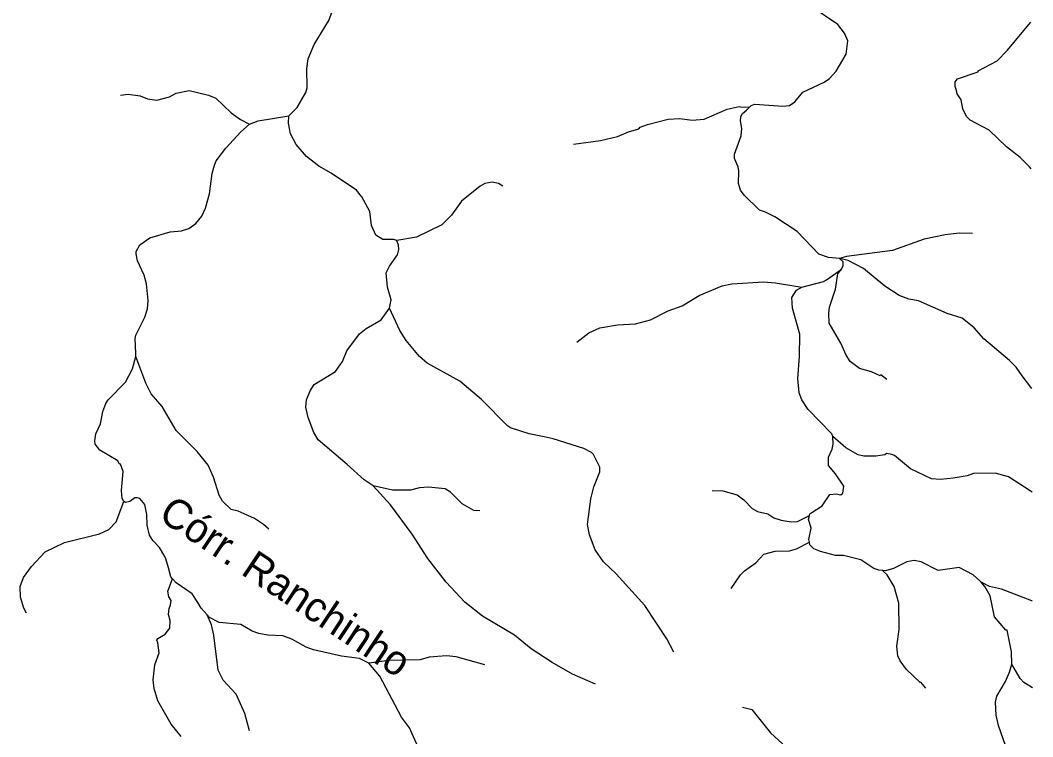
# Model space of a CAD drawing. Extents: x 393 to 446.6, y 8175.5 to 8231.
# Drawn here: x 441.14 to 446.6, y 8192.41 to 8196.27 of the extents above; entities that cross this region are included whole.
import ezdxf
from ezdxf.enums import TextEntityAlignment as Align

# ---------------------------------------------------------------- set-up
doc = ezdxf.new("R2010")
doc.units = 0
doc.header["$LTSCALE"] = 0.064
doc.linetypes.add('LONG_DASHED', pattern=[7.5, 6, -1.5])
doc.layers.add('61', color=7, linetype='Continuous')
doc.layers.add('7', color=7, linetype='Continuous', lineweight=25)
doc.layers.add('9', color=7, linetype='LONG_DASHED', lineweight=25)

msp = doc.modelspace()

# ---------------------------------------------------------------- linework, layer by layer
at = {"layer": '7'}
for points in [[(442.589, 8195.7595), (442.6332, 8195.8043), (442.6803, 8195.8853), (442.6868, 8195.9111), (442.6852, 8196.0145), (442.6932, 8196.0661), (442.7255, 8196.1436), (442.803, 8196.2728), (442.8321, 8196.3503), (442.8676, 8196.5054), (442.8757, 8196.557), (442.8757, 8196.6087), (442.8563, 8196.7637), (442.8256, 8196.8671), (442.7869, 8196.9446), (442.6884, 8197.0996), (442.637, 8197.214)], [(445.0706, 8195.8064), (445.0797, 8195.8147), (445.0984, 8195.8228), (445.2495, 8195.8126), (445.285, 8195.8158), (445.3141, 8195.8352), (445.3576, 8195.8869), (445.4723, 8195.9418), (445.5014, 8195.9611), (445.5369, 8195.9999), (445.5901, 8196.092), (445.5998, 8196.1646), (445.5821, 8196.205), (445.5466, 8196.2518), (445.4077, 8196.3454), (445.3479, 8196.3988), (445.314, 8196.4698), (445.2995, 8196.5344), (445.2968, 8196.6641), (445.2966, 8196.6739)], [(446.5877, 8195.4747), (446.5778, 8195.4847), (446.5284, 8195.5349), (446.4541, 8195.593), (446.3604, 8195.6818), (446.2587, 8195.7367), (446.2393, 8195.7561), (446.2199, 8195.7981), (446.2102, 8195.8465), (446.1892, 8195.8788), (446.1844, 8195.8954), (446.1779, 8195.9176), (446.1779, 8195.9434), (446.1909, 8195.9595), (446.3023, 8195.9967), (446.3023, 8196.0015), (446.404, 8196.0564), (446.4605, 8196.1129), (446.5752, 8196.2518), (446.5857, 8196.2645)], [(441.6822, 8195.8704), (441.7228, 8195.8756), (441.7874, 8195.8675), (441.8261, 8195.8513), (441.8778, 8195.8433), (441.9456, 8195.8626), (441.9811, 8195.882), (442.0521, 8195.8965), (442.1555, 8195.8707), (442.1942, 8195.8546), (442.2782, 8195.7754), (442.3283, 8195.7399), (442.3765, 8195.715)], [(444.1223, 8195.6071), (444.2677, 8195.6269), (444.3581, 8195.6479), (444.4178, 8195.6737), (444.4743, 8195.6899), (444.4808, 8195.6979), (444.5196, 8195.7125), (444.6326, 8195.7415), (444.694, 8195.7447), (444.7618, 8195.7367), (444.8264, 8195.7415), (444.9491, 8195.7948), (445.0137, 8195.8093), (445.0214, 8195.8089), (445.0692, 8195.8065), (445.0706, 8195.8064)], [(445.5551, 8194.9916), (445.4949, 8194.9955), (445.4432, 8195.0149), (445.327, 8195.136), (445.2059, 8195.2151), (445.1558, 8195.2409), (445.1235, 8195.2506), (445.0411, 8195.333), (445.0218, 8195.3588), (445.0104, 8195.3944), (445.0121, 8195.4622), (445.0088, 8195.4848), (444.9894, 8195.53), (444.9894, 8195.5526), (445.025, 8195.6527), (445.0282, 8195.6915), (445.0217, 8195.7335), (445.0234, 8195.7561), (445.0331, 8195.7722), (445.0532, 8195.7905), (445.0706, 8195.8064)], [(442.3765, 8195.715), (442.4236, 8195.7334), (442.589, 8195.7595)], [(443.1697, 8195.0871), (443.1546, 8195.0941), (443.0953, 8195.0924), (443.0565, 8195.1166), (443.0339, 8195.1683), (443.0242, 8195.2442), (442.9823, 8195.3233), (442.9729, 8195.3347), (442.9532, 8195.3588), (442.816, 8195.4509), (442.7497, 8195.488), (442.6835, 8195.5413), (442.6286, 8195.6043), (442.5979, 8195.6624), (442.5866, 8195.7206), (442.589, 8195.7595)], [(441.764, 8194.4621), (441.7632, 8194.48), (441.7599, 8194.5579), (441.7647, 8194.5773), (441.8131, 8194.6742), (441.8277, 8194.7194), (441.8309, 8194.7646), (441.8212, 8194.855), (441.8083, 8194.9003), (441.7728, 8194.9778), (441.7663, 8195.0165), (441.7663, 8195.0278), (441.7857, 8195.0649), (441.839, 8195.1021), (441.9488, 8195.1344), (442.0102, 8195.1392), (442.0489, 8195.1521), (442.0877, 8195.1796), (442.12, 8195.2183), (442.1393, 8195.262), (442.1603, 8195.3395), (442.1749, 8195.4493), (442.1878, 8195.4945), (442.1975, 8195.5171), (442.2491, 8195.5849), (442.3299, 8195.6737), (442.3765, 8195.715)], [(443.7407, 8195.381), (443.7185, 8195.3949), (443.6836, 8195.4019), (443.6444, 8195.3944), (443.6185, 8195.3814), (443.5184, 8195.2991), (443.4651, 8195.2248), (443.4118, 8195.1715), (443.2762, 8195.1053), (443.17, 8195.0871), (443.1697, 8195.0871)], [(446.2707, 8195.1264), (446.199, 8195.1279), (446.1247, 8195.1182), (446.0117, 8195.0956), (445.8405, 8195.0342), (445.5918, 8195.0019), (445.5551, 8194.9916)], [(443.1314, 8194.7232), (443.1389, 8194.7678), (443.1195, 8194.8357), (443.1131, 8194.9132), (443.1308, 8194.9503), (443.1744, 8195.01), (443.1809, 8195.0391), (443.1793, 8195.065), (443.1698, 8195.0869), (443.1697, 8195.0871)], [(445.5633, 8194.931), (445.5749, 8194.9508), (445.5737, 8194.9729), (445.5551, 8194.9916)], [(446.5906, 8194.29), (446.538, 8194.3593), (446.5057, 8194.4045), (446.4702, 8194.4416), (446.3314, 8194.5579), (446.2797, 8194.6176), (446.2151, 8194.6693), (446.1344, 8194.6951), (445.981, 8194.763), (445.9277, 8194.7726), (445.876, 8194.792), (445.7985, 8194.8421), (445.6838, 8194.9373), (445.6015, 8194.9793), (445.5551, 8194.9916)], [(445.3523, 8194.8365), (445.4691, 8194.8663), (445.4852, 8194.876), (445.5633, 8194.931)], [(445.8104, 8194.3388), (445.7778, 8194.3633), (445.7743, 8194.3593), (445.7274, 8194.3803), (445.6629, 8194.398), (445.6128, 8194.4352), (445.5901, 8194.4707), (445.5627, 8194.5353), (445.4997, 8194.6419), (445.4965, 8194.6968), (445.5013, 8194.7291), (445.5336, 8194.826), (445.545, 8194.9083), (445.5633, 8194.931)], [(444.1394, 8194.5395), (444.2047, 8194.5902), (444.2644, 8194.6176), (444.3581, 8194.6338), (444.455, 8194.6386), (444.5357, 8194.6596), (444.6326, 8194.7097), (444.7069, 8194.7355), (444.7989, 8194.792), (444.9233, 8194.8437), (444.975, 8194.855), (445.1461, 8194.8647), (445.2107, 8194.8598), (445.3523, 8194.8365)], [(445.5184, 8194.0324), (445.5126, 8194.0452), (445.3851, 8194.1768), (445.3512, 8194.2285), (445.3382, 8194.2673), (445.3302, 8194.3448), (445.3399, 8194.4626), (445.3415, 8194.5838), (445.3011, 8194.7226), (445.2979, 8194.7807), (445.3238, 8194.8195), (445.3523, 8194.8365)], [(443.0426, 8193.7664), (442.9936, 8193.7973), (442.9032, 8193.8813), (442.7465, 8194.0137), (442.7223, 8194.0541), (442.6916, 8194.1348), (442.6803, 8194.1897), (442.6835, 8194.2285), (442.7029, 8194.2769), (442.7255, 8194.3124), (442.8402, 8194.3819), (442.8773, 8194.4352), (442.9015, 8194.4933), (442.9693, 8194.5854), (443.0049, 8194.6144), (443.0856, 8194.6596), (443.1314, 8194.7232)], [(444.6616, 8192.8703), (444.6244, 8192.9413), (444.5066, 8193.1208), (444.3516, 8193.2919), (444.2838, 8193.3565), (444.2386, 8193.4211), (444.2079, 8193.5018), (444.1966, 8193.5567), (444.216, 8193.6956), (444.2321, 8193.7602), (444.2628, 8193.8409), (444.2628, 8193.8668), (444.2289, 8193.9346), (444.2192, 8193.9459), (444.1772, 8193.9669), (444.0125, 8194.0185), (443.9641, 8194.0298), (443.8834, 8194.046), (443.7832, 8194.0783), (443.7671, 8194.0896), (443.6266, 8194.2317), (443.5087, 8194.3302), (443.3343, 8194.4271), (443.2923, 8194.4626), (443.2212, 8194.5482), (443.1857, 8194.6031), (443.1314, 8194.7232)], [(441.6986, 8193.6817), (441.6904, 8193.6968), (441.6872, 8193.7408), (441.6953, 8193.8425), (441.6807, 8193.8829), (441.6743, 8193.8845), (441.6662, 8193.9007), (441.5693, 8193.9572), (441.5451, 8193.9895), (441.5435, 8194.0089), (441.5483, 8194.046), (441.5742, 8194.0993), (441.5855, 8194.1671), (441.6032, 8194.2091), (441.6145, 8194.2285), (441.7082, 8194.3238), (441.7453, 8194.3964), (441.764, 8194.4621)], [(442.4812, 8193.5318), (442.451, 8193.5583), (442.4042, 8193.5906), (442.331, 8193.6226), (442.3154, 8193.6294), (442.2782, 8193.6391), (442.2314, 8193.6827), (442.2136, 8193.715), (442.1829, 8193.8119), (442.1539, 8193.8765), (442.0941, 8193.9508), (441.9811, 8194.0638), (441.9052, 8194.193), (441.8471, 8194.2608), (441.818, 8194.3189), (441.764, 8194.4621)], [(445.3925, 8193.6064), (445.3949, 8193.6154), (445.4061, 8193.6229), (445.461, 8193.6584), (445.503, 8193.7198), (445.5369, 8193.723), (445.5611, 8193.7166), (445.5724, 8193.7263), (445.5788, 8193.7634), (445.5336, 8193.8313), (445.4949, 8193.8748), (445.4949, 8193.92), (445.5159, 8193.9636), (445.5207, 8193.9911), (445.5184, 8194.0324)], [(446.5919, 8193.7325), (446.582, 8193.7388), (446.4654, 8193.8135), (446.3927, 8193.8344), (446.2764, 8193.8328), (446.2426, 8193.8199), (446.1667, 8193.807), (446.0989, 8193.8005), (446.0504, 8193.8038), (445.9374, 8193.8571), (445.8518, 8193.9297), (445.8373, 8193.9346), (445.8081, 8193.9394), (445.7985, 8193.9329), (445.7501, 8193.9265), (445.6855, 8193.9265), (445.6548, 8193.9329), (445.5886, 8193.9701), (445.5184, 8194.0324)], [(444.2409, 8192.6973), (444.1159, 8192.7509), (444.0061, 8192.8139), (443.893, 8192.8866), (443.8042, 8192.9608), (443.6314, 8193.0626), (443.5362, 8193.1385), (443.436, 8193.2467), (443.3375, 8193.3742), (443.2535, 8193.5051), (443.1357, 8193.6633), (443.0426, 8193.7664)], [(443.6168, 8193.6313), (443.5846, 8193.6326), (443.5216, 8193.6681), (443.4586, 8193.7311), (443.4312, 8193.7505), (443.3408, 8193.7585), (443.2923, 8193.7553), (443.2439, 8193.7424), (443.147, 8193.7424), (443.0426, 8193.7664)], [(444.8692, 8193.7403), (444.9265, 8193.7392), (445.004, 8193.7182), (445.0395, 8193.6907), (445.0847, 8193.6439), (445.1122, 8193.6278), (445.1687, 8193.6148), (445.201, 8193.5938), (445.2398, 8193.5809), (445.2947, 8193.5712), (445.3286, 8193.5729), (445.3892, 8193.6047), (445.3925, 8193.6064)], [(441.1754, 8193.0796), (441.1602, 8193.1063), (441.143, 8193.166), (441.1414, 8193.2241), (441.1592, 8193.2725), (441.2028, 8193.3307), (441.2754, 8193.4098), (441.3804, 8193.4598), (441.5677, 8193.5066), (441.6194, 8193.5309), (441.6581, 8193.5713), (441.6986, 8193.6817)], [(441.9617, 8193.2647), (441.952, 8193.2754), (441.9405, 8193.3231), (441.9262, 8193.3726), (441.9197, 8193.3855), (441.8907, 8193.434), (441.8551, 8193.4711), (441.8374, 8193.5002), (441.8244, 8193.5535), (441.8228, 8193.6116), (441.8131, 8193.6649), (441.7857, 8193.6972), (441.7712, 8193.7004), (441.7583, 8193.7004), (441.7324, 8193.6811), (441.7091, 8193.6759), (441.6986, 8193.6817)], [(445.3928, 8193.4622), (445.3898, 8193.4769), (445.4028, 8193.5374), (445.3869, 8193.586), (445.3925, 8193.6064)], [(444.971, 8193.2128), (445.0217, 8193.2871), (445.0427, 8193.308), (445.1041, 8193.35), (445.1477, 8193.3969), (445.2075, 8193.413), (445.285, 8193.4162), (445.3238, 8193.4259), (445.3898, 8193.4606), (445.3928, 8193.4622)], [(445.7875, 8193.3093), (445.7673, 8193.3109), (445.7403, 8193.3209), (445.6693, 8193.3678), (445.5757, 8193.3904), (445.5337, 8193.3904), (445.4529, 8193.4114), (445.4157, 8193.4259), (445.3957, 8193.4478), (445.3928, 8193.4622)], [(446.3176, 8193.2459), (446.3103, 8193.2532), (446.2748, 8193.2854), (446.199, 8193.3258), (446.0859, 8193.3096), (445.9955, 8193.3565), (445.9567, 8193.3629), (445.918, 8193.3565), (445.8453, 8193.3209), (445.8033, 8193.308), (445.7875, 8193.3093)], [(446.0204, 8192.6749), (445.9936, 8192.7086), (445.989, 8192.7057), (445.9163, 8192.7768), (445.8808, 8192.8236), (445.8695, 8192.8495), (445.8631, 8192.9011), (445.876, 8192.9916), (445.8744, 8193.1337), (445.8501, 8193.2241), (445.8114, 8193.2855), (445.7882, 8193.3086), (445.7875, 8193.3093)], [(442.0085, 8192.4155), (441.9536, 8192.4813), (441.8826, 8192.6072), (441.8678, 8192.6566), (441.8632, 8192.6718), (441.8567, 8192.7203), (441.8664, 8192.801), (441.889, 8192.8656), (441.8817, 8192.9193), (441.8777, 8192.934), (441.8824, 8192.9423), (441.9214, 8192.9657), (441.9472, 8192.9996), (441.9488, 8193.04), (441.9407, 8193.0723), (441.9439, 8193.1046), (441.9512, 8193.1248), (441.955, 8193.1473), (441.9423, 8193.1676), (441.9359, 8193.1982), (441.9614, 8193.2638), (441.9617, 8193.2647)], [(442.1478, 8193.0698), (442.1167, 8193.1062), (442.0972, 8193.1374), (442.0683, 8193.1837), (441.9811, 8193.2434), (441.9617, 8193.2647)], [(446.483, 8192.8048), (446.4815, 8192.8721), (446.4573, 8192.9883), (446.4508, 8192.9883), (446.3895, 8193.0594), (446.3669, 8193.1724), (446.3374, 8193.2238), (446.3176, 8193.2459)], [(446.5933, 8193.145), (446.5905, 8193.1461), (446.4283, 8193.2095), (446.3637, 8193.2241), (446.3176, 8193.2459)], [(443.0188, 8192.8098), (442.9694, 8192.8349), (442.8725, 8192.8478), (442.7207, 8192.8817), (442.6819, 8192.8962), (442.6044, 8192.9399), (442.556, 8192.9576), (442.4753, 8192.9608), (442.4268, 8192.9705), (442.3913, 8192.9834), (442.3299, 8193.019), (442.2137, 8193.0287), (442.1601, 8193.0554), (442.1478, 8193.0698)], [(442.3761, 8192.4464), (442.3509, 8192.5394), (442.304, 8192.6428), (442.2346, 8192.7187), (442.2072, 8192.772), (442.1846, 8192.9608), (442.1716, 8193.0174), (442.1478, 8193.0698)], [(443.6437, 8192.8007), (443.4893, 8192.8446), (443.4377, 8192.8494), (443.344, 8192.843), (443.2956, 8192.8284), (443.1291, 8192.8243), (443.0188, 8192.8098)], [(443.8977, 8192.3492), (443.8317, 8192.3618), (443.78, 8192.3618), (443.7154, 8192.3537), (443.5249, 8192.3117), (443.449, 8192.2859), (443.3682, 8192.2859), (443.3262, 8192.3069), (443.3052, 8192.3278), (443.2745, 8192.3812), (443.239, 8192.4619), (443.1954, 8192.52), (443.0791, 8192.7397), (443.0188, 8192.8098)], [(446.5958, 8192.1499), (446.5814, 8192.1612), (446.5488, 8192.1868), (446.5197, 8192.2252), (446.4961, 8192.2778), (446.4638, 8192.3246), (446.4121, 8192.4748), (446.3992, 8192.5297), (446.3959, 8192.6008), (446.4024, 8192.6331), (446.4492, 8192.7106), (446.4702, 8192.7623), (446.483, 8192.8048)], [(446.5945, 8192.677), (446.5802, 8192.6858), (446.5478, 8192.7057), (446.5283, 8192.7267), (446.483, 8192.8048)]]:
    msp.add_lwpolyline(points, dxfattribs=at)
at = {"layer": '9'}
msp.add_lwpolyline([(445.0324, 8192.5739), (445.0816, 8192.5598), (445.1825, 8192.4349), (445.3305, 8192.2992), (445.3523, 8192.1667), (445.3882, 8192.0628), (445.4025, 8191.9901), (445.4333, 8191.9483), (445.4496, 8191.9103), (445.4523, 8191.8381), (445.4281, 8191.7992), (445.3987, 8191.7671)], dxfattribs=at)

# ---------------------------------------------------------------- texts
at = {"layer": '61'}
msp.add_text('Córr. Ranchinho', height=0.16, rotation=326.379, dxfattribs=at).set_placement((442.5271, 8193.1583), align=Align.CENTER)

doc.saveas('drawing.dxf')
